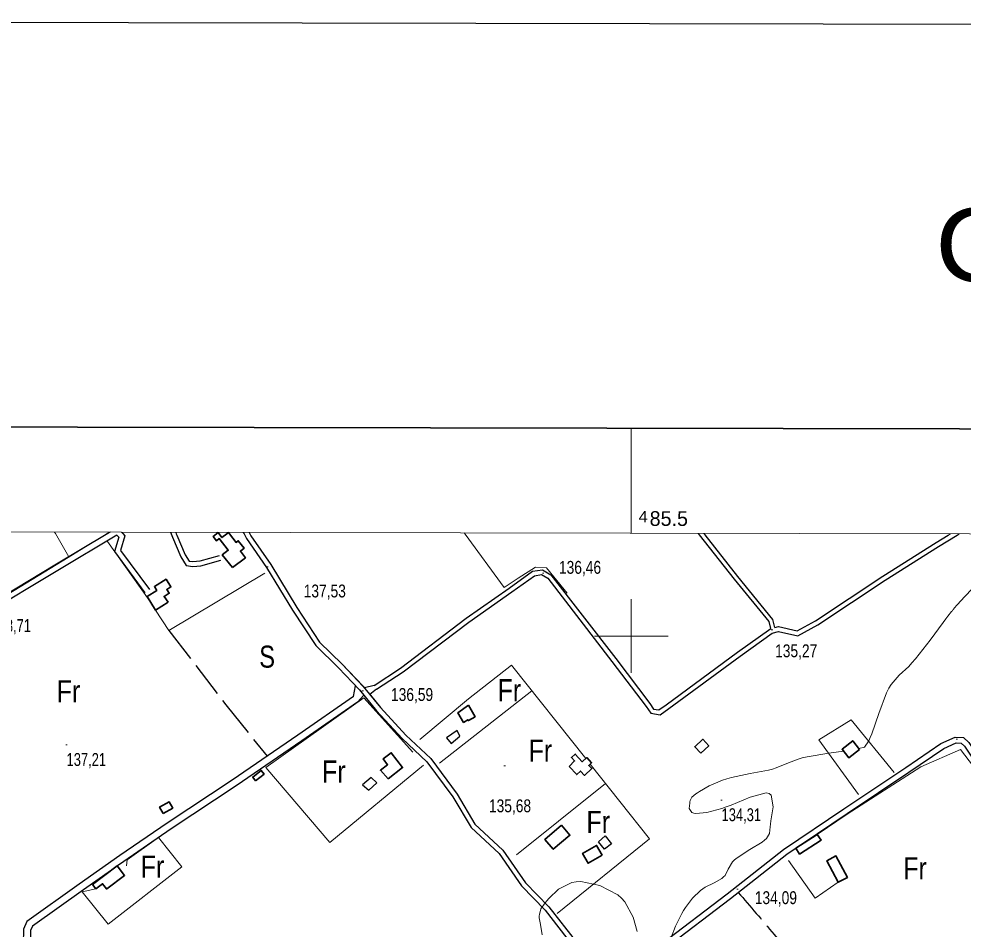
# Model space of a CAD drawing. Extents: x 483855 to 488461, y 4388206 to 4391419.
# Drawn here: x 485084 to 485725, y 4390801 to 4391419 of the extents above; entities that cross this region are included whole.
import ezdxf
from ezdxf.enums import TextEntityAlignment as Align

# ---------------------------------------------------------------- set-up
doc = ezdxf.new("R2010")
doc.units = 0
doc.header["$LTSCALE"] = 4
doc.linetypes.add('DOTTED', pattern=[1.5, 0.3, -1.2])
doc.linetypes.add('LONG_DASHED', pattern=[7.5, 6, -1.5])
for name, color, linetype, lineweight in [('1', 7, 'Continuous', 13), ('2', 7, 'DOTTED', 13), ('21', 7, 'Continuous', 25), ('25', 7, 'LONG_DASHED', 25), ('36', 7, 'Continuous', 25), ('38', 7, 'Continuous', 25), ('47', 7, 'Continuous', 35), ('51', 7, 'Continuous', 13), ('7', 7, 'Continuous', 13), ('9', 7, 'Continuous', 13)]:
    doc.layers.add(name, color=color, linetype=linetype, lineweight=lineweight)
doc.layers.add('31', color=7, linetype='Continuous')

msp = doc.modelspace()

# ---------------------------------------------------------------- linework, layer by layer
at = {"layer": '1'}
for p, q in [((485500, 4391069.93), (485500, 4391141.32)), ((485500, 4391025), (485500, 4390975)), ((485475, 4391000), (485525, 4391000))]:
    msp.add_line(p, q, dxfattribs=at)
at = {"layer": '1', "lineweight": 25}
msp.add_lwpolyline([(483860.86, 4391419.44), (488460.85, 4391410.69), (488454.76, 4388205.69), (483854.77, 4388214.44)], close=True, dxfattribs=at)
at = {"layer": '1', "lineweight": 35}
msp.add_lwpolyline([(484045.03, 4391144.08), (487760.33, 4391137.02), (487755.66, 4388682.02), (484040.36, 4388689.09)], close=True, dxfattribs=at)
at = {"layer": '1'}
msp.add_lwpolyline([(484115.5, 4391072.6), (487689.7, 4391065.7), (487685.8, 4388753.5), (484110.5, 4388760.3)], close=True, dxfattribs=at)
at = {"layer": '21'}
for points in [[(485377.74, 4390927.04), (485383.58, 4390931.93), (485381.63, 4390935.75), (485374.51, 4390930.86)], [(485321.76, 4390895.29), (485327.07, 4390900.4), (485323.17, 4390903.85), (485317.4, 4390898.96)], [(485481.83, 4390855.2), (485477.77, 4390860.29), (485482.34, 4390864.28), (485486.55, 4390858.88)]]:
    msp.add_lwpolyline(points, close=True, dxfattribs=at)
at = {"layer": '25'}
msp.add_lwpolyline([(485185.88, 4391003.84), (485224.59, 4390953.19), (485252.59, 4390918.41)], dxfattribs=at)
at = {"layer": '36'}
for p, q in [((485236.37, 4391070.44), (485236.89, 4391069.49)), ((485240.31, 4391070.43), (485240.83, 4391069.49)), ((485240.31, 4391070.43), (485240.83, 4391069.49))]:
    msp.add_line(p, q, dxfattribs=at)
for points in [[(485236.89, 4391069.49), (485238.59, 4391066.41), (485252.27, 4391046.71), (485269.87, 4391017.56), (485285.59, 4390993.65), (485301.14, 4390978.45), (485315.27, 4390963.55), (485326.99, 4390949.31), (485344.35, 4390930.36), (485361.18, 4390914.64), (485378.85, 4390890.74), (485391.11, 4390870.05), (485410.19, 4390852.3), (485425.46, 4390830.2), (485441.39, 4390813.87), (485460.18, 4390789.75)], [(485240.83, 4391069.49), (485241.52, 4391068.23), (485255.16, 4391048.58), (485272.78, 4391019.4), (485288.26, 4390995.85), (485303.59, 4390980.87), (485317.85, 4390965.83), (485329.59, 4390951.57), (485346.8, 4390932.78), (485363.76, 4390916.94), (485381.72, 4390892.65), (485393.82, 4390872.23), (485412.81, 4390854.56), (485428.13, 4390832.4), (485443.99, 4390816.14), (485462.83, 4390791.94)], [(485240.83, 4391069.49), (485241.52, 4391068.23), (485255.16, 4391048.58), (485272.78, 4391019.4), (485288.26, 4390995.85), (485303.59, 4390980.87), (485317.76, 4390965.93)], [(485322.84, 4390959.77), (485329.59, 4390951.57), (485346.8, 4390932.78), (485363.76, 4390916.94), (485381.72, 4390892.65), (485393.82, 4390872.23), (485412.81, 4390854.56), (485428.13, 4390832.4), (485443.99, 4390816.14), (485462.83, 4390791.94)]]:
    msp.add_lwpolyline(points, dxfattribs=at)
at = {"layer": '38'}
for p, q in [((485145.85, 4391070.61), (485144.28, 4391069.67)), ((485153.74, 4391070.6), (485154.62, 4391069.65)), ((485186.94, 4391070.53), (485187.32, 4391069.59)), ((485190.49, 4391070.52), (485190.88, 4391069.58)), ((485546.45, 4391068.89), (485545.7, 4391069.84)), ((485550.1, 4391068.89), (485549.36, 4391069.83)), ((485715.31, 4391068.57), (485716.84, 4391069.51)), ((485721.36, 4391068.56), (485722.89, 4391069.5)), ((485311.17, 4390959), (485312.71, 4390966.26)), ((485325.24, 4390966.49), (485318.65, 4390964.87)), ((485313.9, 4390955.09), (485318.28, 4390959.9)), ((485326.98, 4390963.84), (485322.42, 4390960.29))]:
    msp.add_line(p, q, dxfattribs=at)
for points in [[(485144.28, 4391069.67), (485108.39, 4391048.12), (485057.58, 4391017.73), (485012.02, 4390989.08), (484997.26, 4390978.85), (484995.24, 4390976.6), (485001.11, 4390961.53)], [(485150.45, 4391068.7), (485110.45, 4391044.68), (485059.68, 4391014.31), (485014.23, 4390985.73), (484999.93, 4390975.82), (484999.88, 4390975.76), (485004.85, 4390962.99)], [(485150.45, 4391068.7), (485151.86, 4391067.18), (485148.97, 4391057.47), (485169.57, 4391029.45)], [(485154.62, 4391069.65), (485156.02, 4391068.15), (485153.05, 4391058.18), (485172.56, 4391031.65)], [(485187.32, 4391069.59), (485188.26, 4391067.28), (485193.99, 4391053.78), (485197.54, 4391047.91), (485202.16, 4391047.38), (485207.64, 4391047.84), (485221.08, 4391051.62)], [(485190.88, 4391069.58), (485191.3, 4391068.55), (485196.93, 4391055.28), (485199.52, 4391051), (485202.21, 4391050.69), (485207.05, 4391051.1), (485220.19, 4391054.79)], [(485326.98, 4390963.84), (485344.98, 4390975.7), (485389.75, 4391009.56), (485418.79, 4391029.99), (485434.22, 4391041.07), (485439.02, 4391041.83), (485443.3, 4391039.29), (485486.91, 4390982.75), (485510.15, 4390952.27), (485513.34, 4390947.55), (485519.57, 4390946.51), (485525.53, 4390950.74), (485573.93, 4390986.45), (485595.72, 4391001.98), (485600.04, 4391003.2), (485613.25, 4391000.2), (485626.79, 4391007.63), (485672.58, 4391038.06), (485708.72, 4391060.82), (485721.36, 4391068.56)], [(485594.76, 4391005.19), (485593.61, 4391010.04), (485570.24, 4391038.65), (485546.45, 4391068.89)], [(485597.53, 4391005.79), (485596.22, 4391011.38), (485572.47, 4391040.44), (485550.1, 4391068.89)], [(485597.53, 4391005.79), (485599.95, 4391006.47), (485612.78, 4391003.56), (485625.15, 4391010.34), (485670.86, 4391040.72), (485707.05, 4391063.51), (485715.31, 4391068.57)], [(485325.24, 4390966.49), (485343.15, 4390978.29), (485387.88, 4391012.12), (485416.95, 4391032.57), (485432.98, 4391044.08), (485439.66, 4391045.14), (485445.44, 4391041.7), (485489.42, 4390984.68), (485512.72, 4390954.12), (485515.2, 4390950.45), (485518.8, 4390949.85), (485523.67, 4390953.31), (485572.07, 4390989.02), (485594.76, 4391005.19)], [(485311.17, 4390959), (485273.41, 4390932.69), (485228.9, 4390902.16), (485184.76, 4390872.9), (485152.54, 4390850.87), (485124.97, 4390831.4), (485089.4, 4390806.02), (485087.11, 4390800.89), (485087.12, 4390796.59), (485086.17, 4390791.06), (485078.91, 4390785.27), (485050.68, 4390770.45), (485010.21, 4390750.37), (484988.21, 4390740.68), (484987.9, 4390738), (484987.22, 4390733.35), (484988.91, 4390729.82), (485021.04, 4390685.75), (485063.44, 4390630.98), (485109.89, 4390570.75), (485133.09, 4390539.47), (485133.9, 4390536.4), (485133.44, 4390530.95)], [(485313.9, 4390955.09), (485276.12, 4390928.77), (485231.57, 4390898.21), (485187.42, 4390868.95), (485155.26, 4390846.95), (485150.83, 4390843.82)], [(485484.09, 4390765.62), (485520.58, 4390790.78), (485565.16, 4390824.83), (485603.51, 4390855.05), (485644.49, 4390882.72), (485686.53, 4390910.77), (485710.42, 4390927.08), (485719.98, 4390931.28), (485725.74, 4390931), (485729.29, 4390927.74), (485765.68, 4390872.99), (485798.54, 4390825.11), (485825.46, 4390783.37), (485847.11, 4390755.57), (485864.56, 4390728.75), (485879.65, 4390706.38)], [(485487.07, 4390761.68), (485522.88, 4390787.67), (485567.53, 4390821.78), (485605.79, 4390851.92), (485646.65, 4390879.5), (485688.7, 4390907.56), (485712.31, 4390923.68), (485720.7, 4390927.37), (485724.15, 4390927.2), (485726.32, 4390925.21), (485762.47, 4390870.82), (485795.31, 4390822.96), (485822.3, 4390781.12), (485843.95, 4390753.32), (485861.33, 4390726.61), (485876.45, 4390704.2), (485896.67, 4390661.98), (485921.44, 4390613.92), (485950.81, 4390554.58), (485972.61, 4390514.7)], [(485146.87, 4390841.02), (485127.73, 4390827.51), (485093.22, 4390802.89), (485091.88, 4390799.88), (485091.89, 4390796.19), (485090.56, 4390788.47), (485081.53, 4390781.26), (485052.84, 4390766.21), (485012.23, 4390746.05), (484992.63, 4390737.42), (484992.63, 4390737.39), (484992.15, 4390734.1), (484993.02, 4390732.28), (485024.85, 4390688.62), (485067.21, 4390633.89), (485113.69, 4390573.63), (485137.47, 4390541.57), (485138.72, 4390536.82), (485138.44, 4390533.46)]]:
    msp.add_lwpolyline(points, dxfattribs=at)
at = {"layer": '38', "linetype": 'LONG_DASHED'}
msp.add_spline([(485572.68, 4390825.83), (485596.99, 4390797.25), (485630.74, 4390754.62), (485657.73, 4390718.13)], degree=3, dxfattribs=at)
at = {"layer": '47'}
for points in [[(485218.25, 4391069.53), (485215.96, 4391067.79), (485218.19, 4391064.83), (485220.11, 4391066.29), (485226.17, 4391058.3), (485222.08, 4391055.2), (485229.02, 4391046.52)], [(485219.91, 4391069.53), (485219.3, 4391070.33), (485218.25, 4391069.53)], [(485225.29, 4391069.52), (485221.9, 4391066.93), (485219.91, 4391069.53)], [(485226.98, 4391069.51), (485226.36, 4391070.33), (485225.29, 4391069.52)], [(485229.02, 4391046.52), (485237.86, 4391053.29), (485234.4, 4391057.8), (485236.88, 4391059.7), (485232.99, 4391064.77), (485231.48, 4391063.62), (485226.98, 4391069.51)]]:
    msp.add_lwpolyline(points, dxfattribs=at)
for points in [[(485185.4, 4391022.97), (485176.85, 4391017.63), (485171.02, 4391026.95), (485177.63, 4391031.09), (485176.01, 4391033.65), (485183.93, 4391038.67), (485187.23, 4391033.46), (485184.42, 4391031.69), (485186.04, 4391029.09), (485182.6, 4391026.95)], [(485389.32, 4390953.09), (485393.84, 4390945.22), (485389.32, 4390942.63), (485389.01, 4390943.14), (485386.03, 4390941.34), (485382.11, 4390947.82)], [(485547.21, 4390920.42), (485552.64, 4390925.43), (485548.54, 4390929.87), (485543.11, 4390924.86)], [(485655.15, 4390922.92), (485647.87, 4390917.2), (485643.22, 4390923.12), (485650.5, 4390928.84)], [(485334.8, 4390903.12), (485344.68, 4390910.63), (485336.95, 4390920.79), (485331.39, 4390916.56), (485334.42, 4390912.57), (485329.55, 4390908.88)], [(485457.88, 4390911.34), (485462.91, 4390905.88), (485465.51, 4390908.29), (485468.22, 4390905.36), (485473.21, 4390909.97), (485471.15, 4390912.19), (485473.02, 4390913.92), (485469.77, 4390917.41), (485466.75, 4390914.6), (485461.89, 4390919.82), (485459.37, 4390917.48), (485461.53, 4390915.14)], [(485244.71, 4390901.77), (485250.49, 4390906.23), (485248.6, 4390908.68), (485242.82, 4390904.22)], [(485182.03, 4390879.46), (485188.47, 4390883.13), (485185.99, 4390887.49), (485179.55, 4390883.82)], [(485452.62, 4390871.43), (485441.33, 4390861.85), (485447.02, 4390855.14), (485458.31, 4390864.72)], [(485611.82, 4390855.86), (485626.34, 4390865.27), (485628.92, 4390861.29), (485614.4, 4390851.88)], [(485480.26, 4390851.14), (485470.67, 4390845.69), (485466.9, 4390852.32), (485476.49, 4390857.77)], [(485640.59, 4390832.73), (485632.81, 4390847.23), (485639.06, 4390850.58), (485646.84, 4390836.08)], [(485133.95, 4390831.15), (485150.73, 4390843.93), (485155.73, 4390837.35), (485143.76, 4390828.26), (485143.63, 4390828.42), (485143.36, 4390828.22), (485140.78, 4390831.7), (485136.17, 4390828.29)]]:
    msp.add_lwpolyline(points, close=True, dxfattribs=at)
at = {"layer": '51'}
for p, q in [((485108.23, 4391070.68), (485108.77, 4391069.74)), ((485108.77, 4391069.74), (485117.84, 4391053.8)), ((485145.31, 4391070.61), (485143.8, 4391069.68)), ((485386.52, 4391070.15), (485387.21, 4391069.2)), ((485172.55, 4391024.51), (485144.15, 4391064.38)), ((485432.44, 4390962.87), (485369.66, 4390913.67))]:
    msp.add_line(p, q, dxfattribs=at)
for points in [[(485143.8, 4391069.68), (485117.46, 4391053.39), (484995.91, 4390979.38), (484958.97, 4391041.73)], [(485387.21, 4391069.2), (485413.65, 4391033.02), (485423.09, 4391039.49), (485434.93, 4391046.86), (485442.51, 4391046.49), (485456.56, 4391029.19)], [(485250.93, 4391042.73), (485185.88, 4391003.84), (485176.85, 4391017.63)], [(485356.43, 4390929.78), (485389.32, 4390957.44), (485418.53, 4390980.37), (485469.08, 4390916.76)], [(485358.78, 4390912.31), (485295.11, 4390859.84), (485251.67, 4390910.63), (485318.35, 4390958.15), (485351.57, 4390921.07)], [(485678.73, 4390907.43), (485649.41, 4390943.16), (485627.38, 4390929.47), (485654.37, 4390892.46)], [(485647.59, 4390730.5), (485671.34, 4390700.6), (485811.68, 4390796.85), (485779.43, 4390843.01), (485738.52, 4390903.63), (485723.64, 4390922.96), (485696.65, 4390911.13), (485646.74, 4390879.02), (485626.34, 4390865.27)], [(485472.05, 4390913.01), (485512.35, 4390862.3), (485449.57, 4390811.41)], [(485482.59, 4390899.76), (485450.59, 4390874.28), (485422.05, 4390851.35)], [(485136.17, 4390828.29), (485126.98, 4390826.34), (485144.65, 4390804.24), (485194.62, 4390843.25), (485178.83, 4390863.18), (485157.4, 4390847.99), (485156.96, 4390843.79)], [(485640.59, 4390832.73), (485624.86, 4390821.98), (485606.89, 4390847.53)]]:
    msp.add_lwpolyline(points, dxfattribs=at)
at = {"layer": '7'}
for p, q in [((485252.37, 4391047.08), (485253.37, 4391047.08)), ((485439.69, 4391042.81), (485440.69, 4391042.81)), ((485595.1, 4391004.29), (485596.1, 4391004.29)), ((485317.02, 4390962.8), (485318.02, 4390962.8)), ((485720.65, 4390930), (485721.65, 4390930)), ((485115.82, 4390926.16), (485116.82, 4390926.16)), ((485413.5, 4390911.8), (485414.5, 4390911.8)), ((485560.86, 4390888.63), (485561.86, 4390888.63)), ((485571.69, 4390827.97), (485572.69, 4390827.97))]:
    msp.add_line(p, q, dxfattribs=at)
at = {"layer": '9'}
for points in [[(485730.84, 4391031.5), (485723.54, 4391023.63), (485722.1, 4391022.05), (485720.91, 4391020.72), (485718.72, 4391018.09), (485718.2, 4391017.28), (485718.07, 4391017.11), (485717.94, 4391016.97), (485717.53, 4391016.62), (485715.07, 4391013.54), (485713.65, 4391011.67), (485711.92, 4391009.35), (485703.01, 4390997.31), (485693.1, 4390984.58), (485690.74, 4390981.83), (485688.54, 4390979.42), (485681.96, 4390973.49), (485676.48, 4390967.21), (485674.98, 4390964.57), (485673.48, 4390961.54), (485668.11, 4390947.36), (485663.4, 4390933.7), (485662.32, 4390931), (485661.33, 4390928.76), (485658.58, 4390924.62), (485654.62, 4390923.59)], [(485644.23, 4390921.84), (485634.21, 4390920.42), (485619.5, 4390918), (485616.23, 4390917.26), (485613.3, 4390916.49), (485605.61, 4390913.45), (485598.52, 4390910.42), (485595.96, 4390909.66), (485593.15, 4390908.92), (485580.86, 4390906.54), (485568.1, 4390903.96), (485564.99, 4390903.1), (485562.07, 4390902.17), (485553.03, 4390898.3), (485546.45, 4390894.5), (485545.07, 4390893.61), (485543.89, 4390892.8), (485541.22, 4390890.47), (485540.09, 4390888.18), (485539.88, 4390887.4), (485539.71, 4390886.55), (485539.44, 4390882.93), (485541.26, 4390880.04), (485542.4, 4390879.65), (485543.82, 4390879.44), (485551.26, 4390880.17), (485561.43, 4390882.93), (485564.58, 4390884), (485567.86, 4390885.19), (485580.89, 4390890.62), (485591.74, 4390893.44), (485593.65, 4390893), (485595.08, 4390892.03), (485596.3, 4390884.1), (485594.79, 4390874.38), (485594.5, 4390872.28), (485594.27, 4390870.43), (485593.9, 4390865.89), (485591.86, 4390862.45), (485590.58, 4390861.31), (485588.98, 4390860.08), (485580.58, 4390854.94), (485571.97, 4390849.44), (485570.23, 4390847.99), (485568.78, 4390846.56)], [(485568.78, 4390846.56), (485565.85, 4390841.65), (485563.71, 4390837.36), (485562.76, 4390836.32), (485561.64, 4390835.36), (485556.29, 4390832.42), (485550.16, 4390829.31), (485548.55, 4390828.23), (485546.98, 4390827.05), (485541.63, 4390822.01), (485536.77, 4390815.66), (485535.51, 4390813.65), (485534.29, 4390811.53), (485530.16, 4390802.99), (485527.03, 4390795.09)], [(485504.08, 4390799.29), (485501.4, 4390809.02), (485495.73, 4390819.49), (485493.42, 4390821.92), (485490.8, 4390824.15), (485478.65, 4390830.52), (485465.69, 4390833.21), (485462.56, 4390833.12), (485459.62, 4390832.67), (485450.63, 4390828.03), (485444.1, 4390821.72), (485442.71, 4390820.22), (485441.5, 4390818.82), (485438.65, 4390814.66), (485437.59, 4390810.93), (485437.51, 4390809.81), (485437.53, 4390808.64), (485438.37, 4390804.1), (485439.55, 4390797.01)]]:
    msp.add_lwpolyline(points, dxfattribs=at)

# ---------------------------------------------------------------- texts
at = {"layer": '2', "width": 1.15}
msp.add_text('Cas Metge ', height=50, rotation=359.889, dxfattribs=at).set_placement((485902.91, 4391240.55), align=Align.CENTER)
at = {"layer": '2', "width": 1.1}
msp.add_text('4', height=7.5, rotation=359.889, dxfattribs=at).set_placement((485504.99, 4391077.42))
at = {"layer": '2'}
msp.add_text('85.5', height=10, rotation=359.889, dxfattribs=at).set_placement((485512.48, 4391074.91))
at = {"layer": '31'}
for s, width, p in [('S', 0.8, (485252.6, 4390978.56)), ('Fr', 0.85, (485117.59, 4390955)), ('Fr', 0.85, (485417.16, 4390955.78)), ('Fr', 0.85, (485438.23, 4390914.71)), ('Fr', 0.85, (485297.86, 4390900.48)), ('Fr', 0.85, (485477.59, 4390866.23)), ('Fr', 0.85, (485174.65, 4390835.89)), ('Fr', 0.85, (485692.78, 4390834.77))]:
    msp.add_text(s, height=15, dxfattribs=dict(at, width=width)).set_placement(p, align=Align.CENTER)
at = {"layer": '7'}
for s, width, p in [('136,46', 0.8, (485450.88, 4391042.35)), ('137,53', 0.8, (485277.46, 4391026.29)), ('138,71', 0.75, (485065.31, 4391002.77)), ('135,27', 0.8, (485597.74, 4390985.64)), ('136,59', 0.8, (485336.77, 4390955.92)), ('137,21', 0.75, (485116.32, 4390911.79)), ('135,68', 0.8, (485403.31, 4390880.31)), ('134,31', 0.75, (485561.36, 4390874.26)), ('134,09', 0.8, (485583.95, 4390817.87))]:
    msp.add_text(s, height=8.75, dxfattribs=dict(at, width=width)).set_placement(p)

doc.saveas('drawing.dxf')
